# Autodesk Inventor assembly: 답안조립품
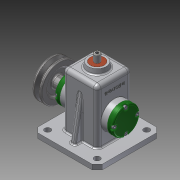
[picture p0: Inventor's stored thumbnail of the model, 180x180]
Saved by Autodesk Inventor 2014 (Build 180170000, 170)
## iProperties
Created: 2016-02
Part Number: 답안조립품
Document SubType Name: Assembly
Designer: SEC
Author: SEC
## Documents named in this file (16)
- C:\Users\SEC\Desktop\460211V1010\답안조립품.iam
- C:\Users\SEC\Desktop\460211V1010\1본체.ipt
- C:\Users\SEC\Desktop\460211V1010\뒤커버.ipt
- C:\Users\SEC\Desktop\460211V1010\베어링 12 x 32 x 10.ipt
- C:\Users\SEC\Desktop\460211V1010\편심축.ipt
- C:\Users\SEC\Desktop\460211V1010\앞커버.ipt
- C:\Users\SEC\Desktop\460211V1010\오일실 12 25 7.ipt
- C:\Users\SEC\Desktop\460211V1010\링크.ipt
- C:\Users\SEC\Desktop\460211V1010\핀 5 x 18.ipt
- C:\Users\SEC\Desktop\460211V1010\고정핀 1.2 x 10.ipt
- C:\Users\SEC\Desktop\460211V1010\슬라이드.ipt
- C:\Users\SEC\Desktop\460211V1010\부시.ipt
- C:\Users\SEC\Desktop\460211V1010\키 4 x 4 x 10.ipt
- C:\Users\SEC\Desktop\460211V1010\V벨트풀리.ipt
- C:\Users\SEC\Desktop\460211V1010\멈춤나사 M3x8.ipt
- C:\Users\SEC\Desktop\460211V1010\볼트 M4 x 12.ipt
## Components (12 placed, 5 different names)
1. 1본체:1
2. 핀 5 x 18:1 — 각도:1
3. 고정핀 1.2 x 10:1 — 플러쉬:1
4. V벨트풀리:1 — 각도:3
5. ISO 4762 M4 x 12:2
6. ISO 4762 M4 x 12:3
7. ISO 4762 M4 x 12:4
8. ISO 4762 M4 x 12:5
9. ISO 4762 M4 x 12:1
10. ISO 4762 M4 x 12:6
11. ISO 4762 M4 x 12:7
12. ISO 4762 M4 x 12:8
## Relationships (3: Angle 2, Flush 1)
- 각도:1 [Angle]: 핀 5 x 18:1
- 플러쉬:1 [Flush]: 고정핀 1.2 x 10:1
- 각도:3 [Angle]: V벨트풀리:1
